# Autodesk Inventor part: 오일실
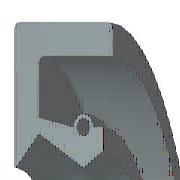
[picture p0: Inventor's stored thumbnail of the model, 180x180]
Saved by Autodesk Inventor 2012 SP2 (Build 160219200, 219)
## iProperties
IsCustomPart: 0
Manager: KYOUNG IL JANG
Company: 한국ATC센터
Created: 2009-02
Part Number: 오일실
Material: 고무
Description: 오일-실
Document SubType Name: Modeling
Standard: KS B 2804
Standards Organization: KS
Language: ko-KR
Size Designation: D - 20 35 8
Categories: <MemberInstance><Categories><Category DisplayName="샤프트 부품" InternalName="7f7aeb1f-a693-4053-b835-cee3144e0d98" Mnemonic="SHFT"><Category DisplayName="실링" Intern
Density: 0.93 g/cm^3
Checked By: KYOUNG IL JANG
Vendor: CBT Solutions
Designer: KYOUNG IL JANG
Author: KYOUNG IL JANG
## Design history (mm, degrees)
revolve "본체" stored, may be unused: angle "d17" = 90 deg
revolve "스프링1" stored, may be unused: angle "d18" = 90 deg
body "Solid1"
sketch "스케치1"
  geometry: L1 (0, 17.5)-(8, 17.5); L2 (8, 15.75)-(1.75, 15.75); L3 (1.75, 11.75)-(4.9, 10); L4 (4.9, 10)-(0, 10); L5 (0, 0)-(9.586, 0) reference; L6 (4.9, 10)-(6.3, 10.875); L7 (0, 18)-(0, -3) reference; L8 (-1.941, 0)-(11.507, 0) reference; L9 (4.2, 12.1)-(1.75, 12.71); L10 (1.75, 12.71)-(1.75, 15.75); L11 (0, 17.5)-(0, 10.088); L12 (4.9, 10)-(0, 10); L13 (1.75, 11.75)-(0.152, 10.028); L14 (8, 17.5)-(8, 15.75); L15 (5.6, 12.1)-(6.3, 12.1); L16 (6.3, 12.1)-(6.3, 10.875); C1 r 0.455 at (4.9, 12.1); A1 r 0.7 centre (4.9, 12.1) between (5.6, 12.1) and (4.2, 12.1); A2 r 0.088 centre (0.088, 10.088) between (0, 10.088) and (0.152, 10.028); 1 further point
  constraints: 28 end point, 5 horizontal alignment, 5 point on line, 4 point on circle, 4 vertical alignment, 3 centre point, 3 tangent, 2 collinear, 2 horizontal, 2 perpendicular, 1 coincident, 1 parallel
  dimensions: "d0" = 35 diameter of L1 L5 (= SD2); "d1" = 1.75 distance of L1.end L2.start (= SD); "d2" = 0.91 diameter of C1 (= SPDI); "d3" = 1.4 diameter of A1 (= SPDA); "d4" = 20 diameter of L3.end L5 (= NND); "d5" = 23.5 diameter of L3.start L5 (= TKDM); "d7" = 25.42 diameter of L9.end L5 (= TKDM + 0.24 x SWDT); "d8" = 1.75 distance between parallel lines of L11 L10 (= SD); "d9" = 4.9 distance from line of L11 C1.centre (= SPDST); "d10" = 24.2 diameter of C1.centre L5 (= HLDM); "d11" = 0.0875 radius of A2 (= 0.25 x LAB); "d12" = 6.3 distance between parallel lines of L11 L16 (= SDI); "d13" = 21.75 diameter of L6.end L5 (= ABDM); "d14" = 8 distance from line of L11 L1.end (= SWDT)
fillet "모깎기1" dims "d6" = 0.3 (= RR)
other parameters: "SD2" = 35 [user parameter; used in 1 equation term], "SWDT" = 8 [user parameter; used in 2 equation terms], "RR" = 0.3 [user parameter; used in 1 equation term], "SD" = 1.75 [user parameter; used in 2 equation terms], "NND" = 20 [user parameter; used in 1 equation term], "SPDA" = 1.4 [user parameter; used in 1 equation term], "SPDI" = 0.91 [user parameter; used in 1 equation term], "TKDM" = 23.5 [user parameter; used in 2 equation terms], "HLDM" = 24.2 [user parameter; used in 1 equation term], "ABDM" = 21.75 [user parameter; used in 1 equation term], "SDI" = 6.3 [user parameter; used in 1 equation term], "SPDST" = 4.9 [user parameter; used in 1 equation term], "LAB" = 0.35 [user parameter; used in 1 equation term], "d15" = 0, "d16" = 0, "d19" = 0
